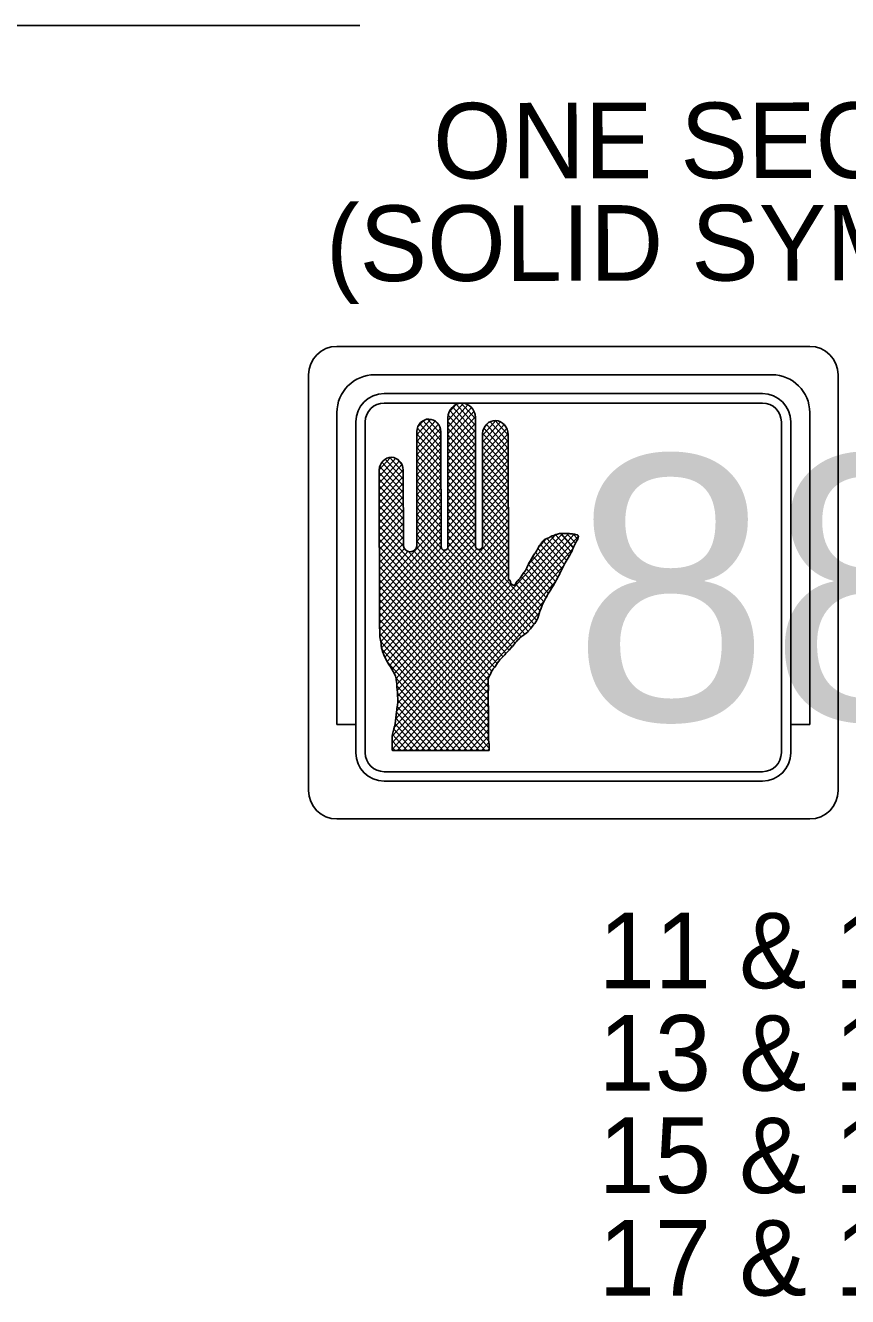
# Model space of a CAD drawing. Extents: x 1845362 to 1846362, y 750211 to 750851.
# Drawn here: x 1845618.5 to 1845662, y 750351.8 to 750419.1 of the extents above; entities that cross this region are included whole.
import ezdxf

# ---------------------------------------------------------------- set-up
doc = ezdxf.new("R2010")
doc.units = 0
doc.layers.add('T_Drafting', color=7, linetype='Continuous')
doc.layers.add('T_Notes', color=7, linetype='Continuous')

msp = doc.modelspace()

# ---------------------------------------------------------------- linework, layer by layer
at = {"layer": 'T_Drafting'}
for p, q in [((1845635.011, 750402.108), (1845660.011, 750402.108)), ((1845633.511, 750400.608), (1845633.511, 750378.608)), ((1845637.011, 750400.608), (1845658.011, 750400.608)), ((1845661.511, 750378.608), (1845661.511, 750400.608)), ((1845637.511, 750399.608), (1845657.511, 750399.608)), ((1845635.011, 750398.608), (1845635.011, 750382.108)), ((1845637.511, 750399.108), (1845657.511, 750399.108)), ((1845640.875, 750398.192), (1845641.697, 750399.105)), ((1845640.875, 750397.839), (1845641.94, 750399.022)), ((1845640.875, 750397.486), (1845642.124, 750398.873)), ((1845640.876, 750397.133), (1845642.259, 750398.669)), ((1845640.89, 750398.467), (1845642.34, 750396.856)), ((1845640.928, 750398.605), (1845641.329, 750399.051)), ((1845640.98, 750398.72), (1845642.339, 750397.21)), ((1845641.126, 750398.911), (1845642.339, 750397.564)), ((1845641.322, 750399.047), (1845642.338, 750397.918)), ((1845641.583, 750399.111), (1845642.338, 750398.272)), ((1845642.049, 750398.946), (1845642.191, 750398.788)), ((1845660.011, 750382.108), (1845660.011, 750398.608)), ((1845636.011, 750398.108), (1845636.011, 750380.608)), ((1845636.511, 750398.108), (1845636.511, 750380.608)), ((1845639.236, 750397.432), (1845639.974, 750398.251)), ((1845639.237, 750397.079), (1845640.206, 750398.156)), ((1845639.237, 750396.726), (1845640.374, 750397.989)), ((1845639.272, 750397.79), (1845640.511, 750396.413)), ((1845639.294, 750397.849), (1845639.605, 750398.195)), ((1845639.388, 750398.013), (1845640.51, 750396.767)), ((1845639.564, 750398.172), (1845640.51, 750397.121)), ((1845639.806, 750398.257), (1845640.51, 750397.475)), ((1845640.231, 750398.138), (1845640.4, 750397.95)), ((1845640.882, 750391.507), (1845640.874, 750398.334)), ((1845640.875, 750398.13), (1845642.34, 750396.502)), ((1845640.875, 750397.776), (1845642.34, 750396.148)), ((1845640.876, 750396.779), (1845642.334, 750398.399)), ((1845640.877, 750396.426), (1845642.338, 750398.05)), ((1845642.338, 750398.353), (1845642.345, 750391.575)), ((1845642.705, 750397.397), (1845643.41, 750398.181)), ((1845642.705, 750397.044), (1845643.668, 750398.113)), ((1845642.706, 750396.691), (1845643.857, 750397.97)), ((1845642.782, 750397.779), (1845644.067, 750396.351)), ((1845642.92, 750397.979), (1845644.067, 750396.704)), ((1845643.112, 750398.119), (1845644.066, 750397.058)), ((1845643.374, 750398.181), (1845644.066, 750397.412)), ((1845658.511, 750380.608), (1845658.511, 750398.108)), ((1845659.011, 750380.608), (1845659.011, 750398.108)), ((1845639.243, 750391.635), (1845639.236, 750397.6)), ((1845639.236, 750397.475), (1845640.511, 750396.059)), ((1845639.237, 750397.121), (1845640.512, 750395.705)), ((1845639.238, 750396.373), (1845640.483, 750397.757)), ((1845639.238, 750396.02), (1845640.51, 750397.433)), ((1845640.509, 750397.586), (1845640.516, 750391.54)), ((1845640.876, 750397.422), (1845642.341, 750395.794)), ((1845640.877, 750396.073), (1845642.339, 750397.697)), ((1845640.877, 750395.72), (1845642.339, 750397.344)), ((1845642.712, 750391.543), (1845642.705, 750397.491)), ((1845642.705, 750397.157), (1845644.068, 750395.643)), ((1845642.706, 750396.338), (1845643.992, 750397.767)), ((1845642.706, 750397.509), (1845644.067, 750395.997)), ((1845642.706, 750395.985), (1845644.063, 750397.492)), ((1845642.707, 750395.631), (1845644.066, 750397.142)), ((1845644.066, 750397.444), (1845644.075, 750389.787)), ((1845639.237, 750396.767), (1845640.512, 750395.351)), ((1845639.238, 750395.667), (1845640.51, 750397.08)), ((1845639.239, 750395.314), (1845640.51, 750396.726)), ((1845640.876, 750397.068), (1845642.341, 750395.44)), ((1845640.876, 750396.714), (1845642.342, 750395.086)), ((1845640.878, 750395.367), (1845642.339, 750396.991)), ((1845640.878, 750395.014), (1845642.34, 750396.638)), ((1845642.706, 750396.803), (1845644.068, 750395.289)), ((1845642.706, 750396.449), (1845644.068, 750394.935)), ((1845642.707, 750395.278), (1845644.067, 750396.789)), ((1845642.708, 750394.925), (1845644.067, 750396.435)), ((1845637.248, 750395.577), (1845637.844, 750396.238)), ((1845637.249, 750395.224), (1845638.119, 750396.19)), ((1845637.249, 750394.87), (1845638.315, 750396.054)), ((1845637.249, 750394.517), (1845638.452, 750395.854)), ((1845637.281, 750395.759), (1845638.523, 750394.379)), ((1845637.395, 750395.986), (1845638.522, 750394.733)), ((1845637.568, 750396.147), (1845638.522, 750395.087)), ((1845637.807, 750396.235), (1845638.522, 750395.441)), ((1845638.21, 750396.14), (1845638.433, 750395.893)), ((1845639.238, 750396.413), (1845640.512, 750394.997)), ((1845639.238, 750396.059), (1845640.513, 750394.643)), ((1845639.239, 750394.96), (1845640.511, 750396.373)), ((1845639.24, 750394.607), (1845640.511, 750396.02)), ((1845640.877, 750396.36), (1845642.342, 750394.732)), ((1845640.877, 750396.006), (1845642.342, 750394.378)), ((1845640.879, 750394.661), (1845642.34, 750396.285)), ((1845640.879, 750394.308), (1845642.341, 750395.932)), ((1845642.706, 750396.095), (1845644.069, 750394.581)), ((1845642.708, 750394.572), (1845644.067, 750396.082)), ((1845637.257, 750387.336), (1845637.248, 750395.579)), ((1845637.248, 750395.441), (1845638.523, 750394.025)), ((1845637.249, 750395.087), (1845638.524, 750393.671)), ((1845637.25, 750394.164), (1845638.521, 750395.577)), ((1845637.25, 750393.811), (1845638.522, 750395.224)), ((1845638.521, 750395.565), (1845638.526, 750391.634)), ((1845639.238, 750395.705), (1845640.513, 750394.289)), ((1845639.239, 750395.351), (1845640.514, 750393.935)), ((1845639.24, 750394.254), (1845640.512, 750395.667)), ((1845639.24, 750393.901), (1845640.512, 750395.314)), ((1845640.878, 750395.652), (1845642.343, 750394.024)), ((1845640.878, 750395.298), (1845642.343, 750393.67)), ((1845640.879, 750393.955), (1845642.341, 750395.578)), ((1845640.88, 750393.601), (1845642.341, 750395.225)), ((1845642.707, 750395.741), (1845644.069, 750394.227)), ((1845642.707, 750395.387), (1845644.069, 750393.873)), ((1845642.708, 750394.219), (1845644.068, 750395.729)), ((1845642.709, 750393.866), (1845644.068, 750395.376)), ((1845637.249, 750394.733), (1845638.524, 750393.317)), ((1845637.251, 750393.458), (1845638.522, 750394.871)), ((1845637.251, 750393.105), (1845638.523, 750394.518)), ((1845639.239, 750394.997), (1845640.514, 750393.581)), ((1845639.24, 750394.643), (1845640.514, 750393.227)), ((1845639.241, 750393.548), (1845640.512, 750394.961)), ((1845639.241, 750393.195), (1845640.513, 750394.608)), ((1845640.878, 750394.944), (1845642.344, 750393.316)), ((1845640.879, 750394.59), (1845642.344, 750392.962)), ((1845640.88, 750393.248), (1845642.342, 750394.872)), ((1845640.881, 750392.895), (1845642.342, 750394.519)), ((1845642.708, 750395.033), (1845644.07, 750393.519)), ((1845642.708, 750394.679), (1845644.07, 750393.165)), ((1845642.709, 750393.513), (1845644.068, 750395.023)), ((1845642.71, 750393.16), (1845644.069, 750394.67)), ((1845637.25, 750394.38), (1845638.524, 750392.963)), ((1845637.25, 750394.026), (1845638.525, 750392.609)), ((1845637.251, 750392.752), (1845638.523, 750394.165)), ((1845637.252, 750392.399), (1845638.523, 750393.812)), ((1845639.24, 750394.289), (1845640.515, 750392.873)), ((1845639.24, 750393.935), (1845640.515, 750392.519)), ((1845639.242, 750392.842), (1845640.513, 750394.255)), ((1845639.242, 750392.489), (1845640.514, 750393.902)), ((1845640.879, 750394.236), (1845642.344, 750392.608)), ((1845640.88, 750393.882), (1845642.345, 750392.254)), ((1845640.881, 750392.542), (1845642.343, 750394.166)), ((1845640.881, 750392.189), (1845642.343, 750393.813)), ((1845642.708, 750394.325), (1845644.071, 750392.811)), ((1845642.709, 750393.971), (1845644.071, 750392.457)), ((1845642.71, 750392.807), (1845644.069, 750394.317)), ((1845642.71, 750392.453), (1845644.069, 750393.963)), ((1845637.25, 750393.672), (1845638.525, 750392.255)), ((1845637.251, 750393.318), (1845638.526, 750391.901)), ((1845637.252, 750392.045), (1845638.524, 750393.458)), ((1845637.252, 750391.692), (1845638.524, 750393.105)), ((1845639.241, 750393.581), (1845640.516, 750392.165)), ((1845639.241, 750393.227), (1845640.516, 750391.811)), ((1845639.242, 750392.136), (1845640.514, 750393.549)), ((1845639.243, 750391.782), (1845640.514, 750393.195)), ((1845640.878, 750391.478), (1845642.344, 750393.107)), ((1845640.88, 750393.528), (1845642.345, 750391.9)), ((1845640.88, 750393.174), (1845642.34, 750391.552)), ((1845640.882, 750391.836), (1845642.343, 750393.46)), ((1845642.709, 750393.617), (1845644.071, 750392.103)), ((1845642.71, 750393.263), (1845644.072, 750391.749)), ((1845642.711, 750392.1), (1845644.07, 750393.61)), ((1845642.711, 750391.747), (1845644.07, 750393.257)), ((1845637.251, 750392.964), (1845638.537, 750391.534)), ((1845637.251, 750392.61), (1845643.629, 750385.523)), ((1845637.253, 750391.339), (1845638.525, 750392.752)), ((1845637.253, 750390.986), (1845638.525, 750392.399)), ((1845637.255, 750389.22), (1845640.515, 750392.842)), ((1845637.255, 750388.867), (1845640.515, 750392.489)), ((1845637.269, 750387.115), (1845642.344, 750392.754)), ((1845637.281, 750386.774), (1845642.345, 750392.4)), ((1845637.55, 750385.659), (1845644.07, 750392.904)), ((1845637.673, 750385.442), (1845644.071, 750392.551)), ((1845639.242, 750392.873), (1845640.532, 750391.439)), ((1845639.242, 750392.519), (1845644.589, 750386.579)), ((1845640.881, 750392.82), (1845645.575, 750387.604)), ((1845640.881, 750392.466), (1845645.435, 750387.406)), ((1845642.71, 750392.909), (1845644.072, 750391.395)), ((1845642.71, 750392.555), (1845644.072, 750391.041)), ((1845637.252, 750392.256), (1845643.481, 750385.334)), ((1845637.252, 750391.902), (1845643.347, 750385.129)), ((1845637.254, 750390.633), (1845638.525, 750392.046)), ((1845637.256, 750388.514), (1845640.516, 750392.136)), ((1845637.256, 750388.161), (1845640.516, 750391.783)), ((1845637.329, 750386.474), (1845642.345, 750392.047)), ((1845637.798, 750385.228), (1845644.071, 750392.198)), ((1845637.922, 750385.012), (1845644.072, 750391.844)), ((1845637.933, 750381.135), (1845647.779, 750392.075)), ((1845637.943, 750381.5), (1845647.548, 750392.172)), ((1845638.048, 750381.97), (1845647.26, 750392.205)), ((1845638.119, 750382.402), (1845646.941, 750392.205)), ((1845639.242, 750392.165), (1845644.432, 750386.4)), ((1845639.243, 750391.811), (1845644.275, 750386.22)), ((1845640.882, 750392.112), (1845645.285, 750387.219)), ((1845640.882, 750391.758), (1845645.128, 750387.039)), ((1845642.711, 750392.201), (1845644.073, 750390.687)), ((1845642.711, 750391.847), (1845644.073, 750390.333)), ((1845645.112, 750390.526), (1845646.568, 750392.143)), ((1845645.714, 750391.548), (1845646.056, 750391.928)), ((1845645.92, 750391.817), (1845647.036, 750390.577)), ((1845646.117, 750391.951), (1845647.158, 750390.794)), ((1845646.342, 750392.055), (1845647.286, 750391.006)), ((1845646.577, 750392.147), (1845647.408, 750391.224)), ((1845646.844, 750392.205), (1845647.51, 750391.464)), ((1845647.162, 750392.205), (1845647.623, 750391.692)), ((1845647.504, 750392.179), (1845647.734, 750391.923)), ((1845637.253, 750391.548), (1845643.204, 750384.935)), ((1845637.253, 750391.194), (1845643.092, 750384.706)), ((1845637.254, 750390.28), (1845638.526, 750391.693)), ((1845637.254, 750389.927), (1845638.589, 750391.409)), ((1845637.255, 750389.573), (1845638.77, 750391.257)), ((1845637.257, 750387.808), (1845640.53, 750391.445)), ((1845637.257, 750387.455), (1845640.74, 750391.324)), ((1845637.378, 750386.175), (1845642.345, 750391.694)), ((1845637.443, 750385.893), (1845642.403, 750391.405)), ((1845637.933, 750380.781), (1845647.472, 750391.381)), ((1845638.043, 750384.793), (1845644.072, 750391.491)), ((1845638.138, 750384.544), (1845644.072, 750391.138)), ((1845638.794, 750391.249), (1845643.788, 750385.7)), ((1845639.071, 750391.295), (1845643.951, 750385.873)), ((1845639.217, 750391.486), (1845644.113, 750386.046)), ((1845640.624, 750391.337), (1845644.76, 750386.742)), ((1845640.861, 750391.427), (1845644.948, 750386.886)), ((1845642.518, 750391.354), (1845645.668, 750387.854)), ((1845642.704, 750391.501), (1845644.073, 750389.979)), ((1845645.517, 750391.204), (1845646.694, 750389.896)), ((1845645.638, 750391.423), (1845646.812, 750390.119)), ((1845645.769, 750391.631), (1845646.924, 750390.348)), ((1845637.253, 750390.84), (1845643.008, 750384.446)), ((1845637.254, 750390.486), (1845643.019, 750384.08)), ((1845638.173, 750384.23), (1845644.073, 750390.785)), ((1845638.198, 750380.722), (1845646.997, 750390.499)), ((1845638.203, 750383.91), (1845644.073, 750390.432)), ((1845645.133, 750390.57), (1845646.324, 750389.246)), ((1845645.253, 750390.79), (1845646.453, 750389.456)), ((1845645.377, 750391.005), (1845646.575, 750389.674)), ((1845637.254, 750390.132), (1845643.005, 750383.742)), ((1845637.254, 750389.778), (1845643.006, 750383.388)), ((1845638.22, 750383.221), (1845644.119, 750389.776)), ((1845638.222, 750383.578), (1845644.073, 750390.079)), ((1845644.607, 750389.74), (1845645.844, 750388.365)), ((1845644.755, 750389.929), (1845645.952, 750388.599)), ((1845644.889, 750390.134), (1845646.071, 750388.82)), ((1845645.027, 750390.334), (1845646.193, 750389.039)), ((1845637.255, 750389.424), (1845643.022, 750383.016)), ((1845637.255, 750389.07), (1845643.023, 750382.661)), ((1845638.164, 750382.805), (1845644.236, 750389.552)), ((1845638.517, 750380.723), (1845646.578, 750389.68)), ((1845644.458, 750389.552), (1845645.75, 750388.117)), ((1845637.256, 750388.716), (1845643.024, 750382.307)), ((1845637.256, 750388.362), (1845643.024, 750381.953)), ((1845638.836, 750380.723), (1845645.996, 750388.68)), ((1845637.256, 750388.008), (1845643.026, 750381.597)), ((1845639.154, 750380.724), (1845645.713, 750388.011)), ((1845637.257, 750387.654), (1845643.041, 750381.228)), ((1845637.259, 750387.298), (1845643.06, 750380.852)), ((1845637.272, 750386.93), (1845642.853, 750380.729)), ((1845637.321, 750386.521), (1845642.535, 750380.729)), ((1845637.393, 750386.088), (1845642.217, 750380.728)), ((1845637.705, 750385.388), (1845641.899, 750380.728)), ((1845638.136, 750384.556), (1845641.582, 750380.727)), ((1845639.473, 750380.724), (1845643.146, 750384.805)), ((1845638.181, 750384.152), (1845641.264, 750380.727)), ((1845638.213, 750383.763), (1845640.946, 750380.726)), ((1845639.791, 750380.725), (1845643.015, 750384.306)), ((1845640.11, 750380.725), (1845643.013, 750383.95)), ((1845638.205, 750383.065), (1845640.31, 750380.725)), ((1845638.225, 750383.396), (1845640.628, 750380.726)), ((1845640.429, 750380.726), (1845643.003, 750383.587)), ((1845640.747, 750380.726), (1845643.011, 750383.242)), ((1845638.123, 750382.448), (1845639.675, 750380.725)), ((1845638.158, 750382.764), (1845639.993, 750380.725)), ((1845641.066, 750380.726), (1845643.023, 750382.901)), ((1845641.384, 750380.727), (1845643.023, 750382.548)), ((1845635.011, 750382.108), (1845636.011, 750382.108)), ((1845638.013, 750381.864), (1845639.039, 750380.724)), ((1845638.088, 750382.134), (1845639.357, 750380.724)), ((1845641.703, 750380.727), (1845643.024, 750382.195)), ((1845642.022, 750380.728), (1845643.024, 750381.842)), ((1845659.011, 750382.108), (1845660.011, 750382.108)), ((1845637.934, 750381.244), (1845638.404, 750380.723)), ((1845637.949, 750381.582), (1845638.721, 750380.723)), ((1845642.34, 750380.728), (1845643.029, 750381.494)), ((1845642.659, 750380.729), (1845643.044, 750381.157)), ((1845637.933, 750380.892), (1845638.086, 750380.722)), ((1845637.959, 750380.722), (1845637.933, 750380.754)), ((1845643.038, 750380.729), (1845637.959, 750380.722)), ((1845642.977, 750380.729), (1845643.061, 750380.822)), ((1845643.062, 750380.723), (1845643.038, 750380.729)), ((1845637.511, 750379.608), (1845657.511, 750379.608)), ((1845637.511, 750379.108), (1845657.511, 750379.108)), ((1845635.011, 750377.108), (1845660.011, 750377.108))]:
    msp.add_line(p, q, dxfattribs=at)
for centre, radius, start, end in [((1845635.011, 750400.608), 1.5, 90, 180), ((1845660.011, 750400.608), 1.5, 0, 90), ((1845637.011, 750398.608), 2, 90, 180), ((1845658.011, 750398.608), 2, 0, 90), ((1845637.511, 750398.108), 1.5, 90, 180), ((1845657.511, 750398.108), 1.5, 0, 90), ((1845637.511, 750398.108), 1, 90, 180), ((1845657.511, 750398.108), 1, 0, 90), ((1845637.511, 750380.608), 1.5, 180, 270), ((1845637.511, 750380.608), 1, 180, 270), ((1845657.511, 750380.608), 1.5, 270, 0), ((1845657.511, 750380.608), 1, 270, 0), ((1845635.011, 750378.608), 1.5, 180, 270), ((1845660.011, 750378.608), 1.5, 270, 0)]:
    msp.add_arc(centre, radius, start, end, dxfattribs=at)
for centre, major_axis, start_param, end_param in [((1845641.607, 750398.297), (0, -0.814), 1.640121, 4.665593), ((1845639.872, 750397.552), (0, -0.709), 1.618611, 4.644084), ((1845643.384, 750397.424), (0, -0.758), 1.597842, 4.623315), ((1845637.884, 750395.531), (0, -0.709), 1.618611, 4.644084), ((1845638.884, 750391.635), (0, -0.398), 4.713646, 7.855239), ((1845640.699, 750391.523), (0, -0.204), 4.633755, 7.775348), ((1845642.526, 750391.561), (0, -0.207), 4.624552, 7.766145)]:
    msp.add_ellipse(centre, major_axis=major_axis, ratio=0.9, start_param=start_param, end_param=end_param, dxfattribs=at)
for points in [[(1845644.074, 750389.788), (1845644.125, 750389.774), (1845644.194, 750389.619), (1845644.283, 750389.5), (1845644.335, 750389.481), (1845644.422, 750389.5), (1845644.476, 750389.58), (1845644.634, 750389.774), (1845644.758, 750389.933), (1845644.828, 750390.049), (1845644.898, 750390.147), (1845645.021, 750390.323), (1845645.091, 750390.48), (1845645.196, 750390.694), (1845645.267, 750390.812), (1845645.39, 750391.027), (1845645.529, 750391.224), (1845645.635, 750391.419), (1845645.757, 750391.614), (1845645.864, 750391.751), (1845646.021, 750391.908), (1845646.214, 750391.988), (1845646.32, 750392.047), (1845646.479, 750392.104), (1845646.619, 750392.164), (1845646.831, 750392.205), (1845647.007, 750392.205), (1845647.235, 750392.205), (1845647.447, 750392.185), (1845647.693, 750392.147), (1845647.763, 750392.106), (1845647.779, 750392.049), (1845647.676, 750391.795), (1845647.605, 750391.657), (1845647.536, 750391.519), (1845647.465, 750391.363), (1845647.429, 750391.265), (1845647.289, 750391.01), (1845647.08, 750390.659), (1845646.798, 750390.091), (1845646.446, 750389.444), (1845646.166, 750388.994), (1845646.007, 750388.7), (1845645.868, 750388.425), (1845645.785, 750388.208), (1845645.742, 750388.097), (1845645.585, 750387.625), (1845645.341, 750387.291), (1845645.147, 750387.057), (1845644.866, 750386.821), (1845644.69, 750386.684), (1845644.233, 750386.174), (1845643.83, 750385.744), (1845643.566, 750385.45), (1845643.337, 750385.116), (1845643.223, 750384.97), (1845643.127, 750384.765), (1845643.021, 750384.568), (1845643.022, 750384.138), (1845643.005, 750383.752), (1845643.005, 750383.398), (1845643.023, 750382.93), (1845643.024, 750382.48), (1845643.024, 750381.756), (1845643.043, 750381.173), (1845643.06, 750380.957), (1845643.061, 750380.799), (1845643.061, 750380.724)], [(1845637.933, 750380.754), (1845637.933, 750381.068), (1845637.949, 750381.595), (1845638.089, 750382.143), (1845638.159, 750382.769), (1845638.211, 750383.121), (1845638.211, 750383.806), (1845638.157, 750384.373), (1845638.103, 750384.666), (1845637.84, 750385.155), (1845637.558, 750385.645), (1845637.399, 750386.055), (1845637.327, 750386.485), (1845637.274, 750386.818), (1845637.274, 750387.032), (1845637.257, 750387.336)]]:
    msp.add_spline(points, degree=3, dxfattribs=at)
at = {"layer": 'T_Notes'}
msp.add_line((1845538.033, 750419.086), (1845636.218, 750419.086), dxfattribs=at)

# ---------------------------------------------------------------- texts
at = {"layer": 'T_Drafting'}
for s, height, p in [('ONE SECTION', 4, (1845640.096, 750410.985)), ('(SOLID SYMBOL)', 4, (1845634.431, 750405.56)), ('88', 14, (1845647.475, 750382.329))]:
    msp.add_text(s, height=height, rotation=0.07203, dxfattribs=at).set_placement(p)
at = {"layer": 'T_Notes'}
for s, p in [('11 & 12', (1845648.843, 750368.155)), ('13 & 14', (1845648.842, 750362.737)), ('15 & 16', (1845648.842, 750357.318)), ('17 & 18', (1845648.852, 750351.9))]:
    msp.add_text(s, height=4, dxfattribs=at).set_placement(p)

doc.saveas('drawing.dxf')
